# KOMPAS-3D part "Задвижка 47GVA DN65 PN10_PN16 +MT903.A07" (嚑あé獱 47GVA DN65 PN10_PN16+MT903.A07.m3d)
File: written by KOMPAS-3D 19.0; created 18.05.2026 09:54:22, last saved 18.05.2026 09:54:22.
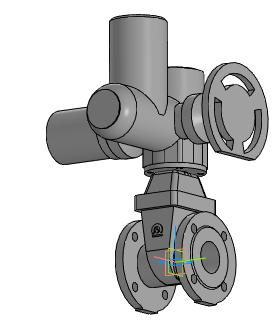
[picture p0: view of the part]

Document properties: Автор: Энергия; Полное имя файла: ..\Задвижка 47GVA DN50_DN1000MT903.A\Задвижка 47GVA DN65 PN10_PN16+MT903.A07.a3d

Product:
- Part/product: Задвижка 47GVA DN65 PN10_PN16 +MT903.A07
    Масса: 88.359
  - Body: Электропривод МТ903.А07 без блока управления
      Масса: 65.4738
  - Body: Задвижка 47GVA DN65 PN10_PN16 без исполнит. мех.
      Масса: 22.8851

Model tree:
1. Операция без истории:1
2. Операция без истории:2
